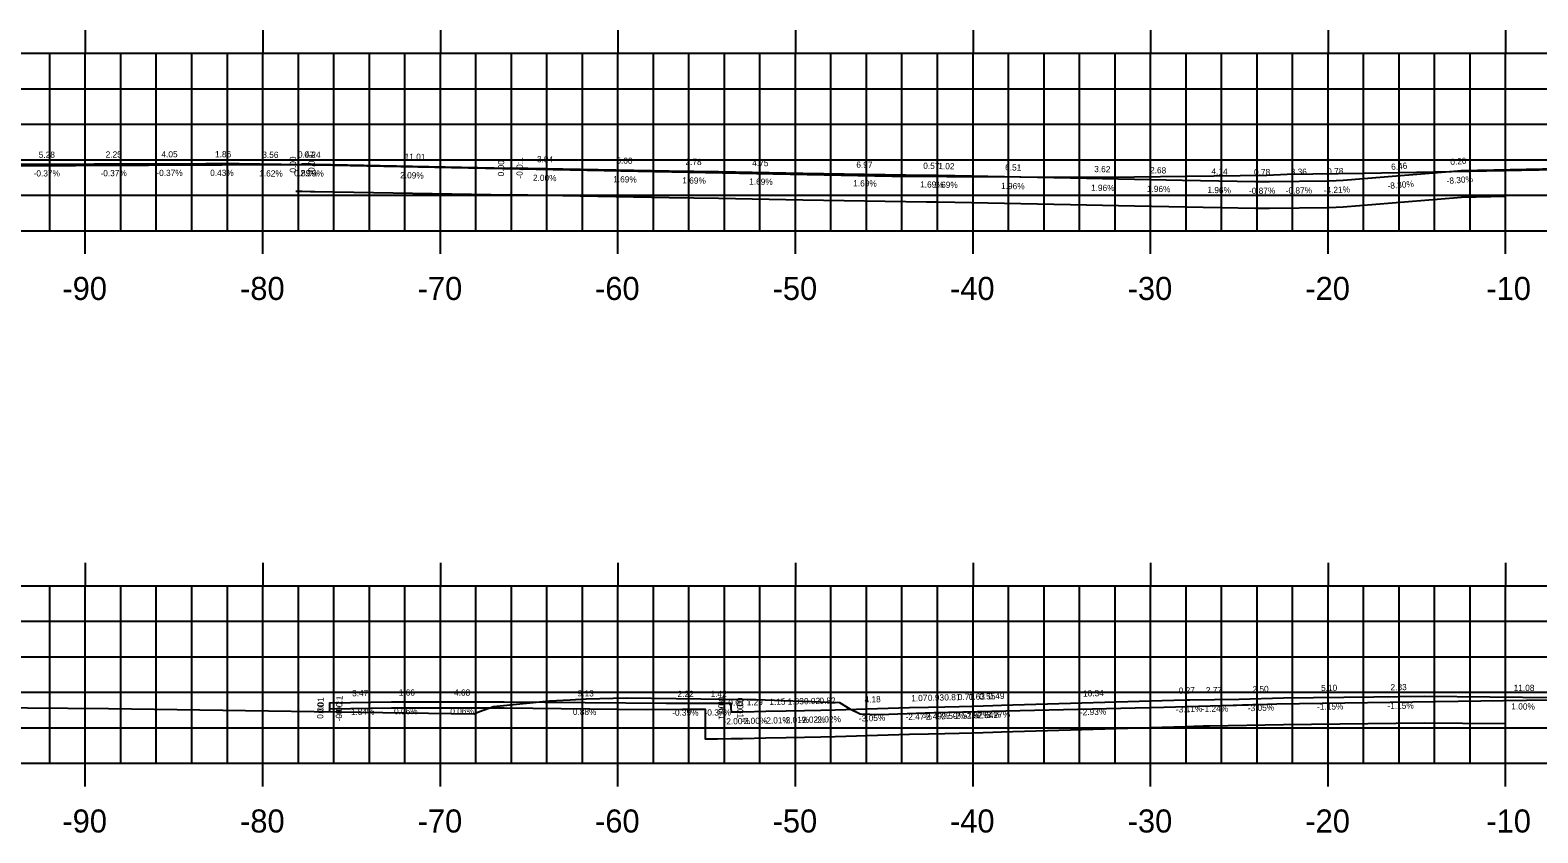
# Model space of a CAD drawing. Extents: x 40011 to 50684, y 49949 to 72236.
# Drawn here: x 41698.9 to 41783.8, y 69085.7 to 69130.9 of the extents above; entities that cross this region are included whole.
import ezdxf

# ---------------------------------------------------------------- set-up
doc = ezdxf.new("R2010")
doc.units = 0
for name, color, linetype in [('10', 7, 'Continuous'), ('51', 7, 'Continuous'), ('53', 7, 'Continuous'), ('55', 7, 'Continuous'), ('57', 7, 'Continuous'), ('58', 7, 'Continuous'), ('59', 7, 'Continuous'), ('60', 7, 'Continuous')]:
    doc.layers.add(name, color=color, linetype=linetype)

msp = doc.modelspace()

# ---------------------------------------------------------------- linework, layer by layer
at = {"layer": '51'}
for p, q in [((41699.977, 69119.597), (41699.977, 69129.597)), ((41703.977, 69119.597), (41703.977, 69129.597)), ((41705.977, 69119.597), (41705.977, 69129.597)), ((41707.977, 69119.597), (41707.977, 69129.597)), ((41709.977, 69119.597), (41709.977, 69129.597)), ((41713.977, 69119.597), (41713.977, 69129.597)), ((41715.977, 69119.597), (41715.977, 69129.597)), ((41717.977, 69119.597), (41717.977, 69129.597)), ((41719.977, 69119.597), (41719.977, 69129.597)), ((41723.977, 69119.597), (41723.977, 69129.597)), ((41725.977, 69119.597), (41725.977, 69129.597)), ((41727.977, 69119.597), (41727.977, 69129.597)), ((41729.977, 69119.597), (41729.977, 69129.597)), ((41733.977, 69119.597), (41733.977, 69129.597)), ((41735.977, 69119.597), (41735.977, 69129.597)), ((41737.977, 69119.597), (41737.977, 69129.597)), ((41739.977, 69119.597), (41739.977, 69129.597)), ((41743.977, 69119.597), (41743.977, 69129.597)), ((41745.977, 69119.597), (41745.977, 69129.597)), ((41747.977, 69119.597), (41747.977, 69129.597)), ((41749.977, 69119.597), (41749.977, 69129.597)), ((41753.977, 69119.597), (41753.977, 69129.597)), ((41755.977, 69119.597), (41755.977, 69129.597)), ((41757.977, 69119.597), (41757.977, 69129.597)), ((41759.977, 69119.597), (41759.977, 69129.597)), ((41763.977, 69119.597), (41763.977, 69129.597)), ((41765.977, 69119.597), (41765.977, 69129.597)), ((41767.977, 69119.597), (41767.977, 69129.597)), ((41769.977, 69119.597), (41769.977, 69129.597)), ((41773.977, 69119.597), (41773.977, 69129.597)), ((41775.977, 69119.597), (41775.977, 69129.597)), ((41777.977, 69119.597), (41777.977, 69129.597)), ((41779.977, 69119.597), (41779.977, 69129.597)), ((41651.977, 69119.597), (41931.977, 69119.597)), ((41701.977, 69118.297), (41701.977, 69119.597)), ((41711.977, 69118.297), (41711.977, 69119.597)), ((41721.977, 69118.297), (41721.977, 69119.597)), ((41731.977, 69118.297), (41731.977, 69119.597)), ((41741.977, 69118.297), (41741.977, 69119.597)), ((41751.977, 69118.297), (41751.977, 69119.597)), ((41761.977, 69118.297), (41761.977, 69119.597)), ((41771.977, 69118.297), (41771.977, 69119.597)), ((41781.977, 69118.297), (41781.977, 69119.597)), ((41699.977, 69089.597), (41699.977, 69099.597)), ((41703.977, 69089.597), (41703.977, 69099.597)), ((41705.977, 69089.597), (41705.977, 69099.597)), ((41707.977, 69089.597), (41707.977, 69099.597)), ((41709.977, 69089.597), (41709.977, 69099.597)), ((41713.977, 69089.597), (41713.977, 69099.597)), ((41715.977, 69089.597), (41715.977, 69099.597)), ((41717.977, 69089.597), (41717.977, 69099.597)), ((41719.977, 69089.597), (41719.977, 69099.597)), ((41723.977, 69089.597), (41723.977, 69099.597)), ((41725.977, 69089.597), (41725.977, 69099.597)), ((41727.977, 69089.597), (41727.977, 69099.597)), ((41729.977, 69089.597), (41729.977, 69099.597)), ((41733.977, 69089.597), (41733.977, 69099.597)), ((41735.977, 69089.597), (41735.977, 69099.597)), ((41737.977, 69089.597), (41737.977, 69099.597)), ((41739.977, 69089.597), (41739.977, 69099.597)), ((41743.977, 69089.597), (41743.977, 69099.597)), ((41745.977, 69089.597), (41745.977, 69099.597)), ((41747.977, 69089.597), (41747.977, 69099.597)), ((41749.977, 69089.597), (41749.977, 69099.597)), ((41753.977, 69089.597), (41753.977, 69099.597)), ((41755.977, 69089.597), (41755.977, 69099.597)), ((41757.977, 69089.597), (41757.977, 69099.597)), ((41759.977, 69089.597), (41759.977, 69099.597)), ((41763.977, 69089.597), (41763.977, 69099.597)), ((41765.977, 69089.597), (41765.977, 69099.597)), ((41767.977, 69089.597), (41767.977, 69099.597)), ((41769.977, 69089.597), (41769.977, 69099.597)), ((41773.977, 69089.597), (41773.977, 69099.597)), ((41775.977, 69089.597), (41775.977, 69099.597)), ((41777.977, 69089.597), (41777.977, 69099.597)), ((41779.977, 69089.597), (41779.977, 69099.597)), ((41651.977, 69089.597), (41931.977, 69089.597)), ((41701.977, 69088.297), (41701.977, 69089.597)), ((41711.977, 69088.297), (41711.977, 69089.597)), ((41721.977, 69088.297), (41721.977, 69089.597)), ((41731.977, 69088.297), (41731.977, 69089.597)), ((41741.977, 69088.297), (41741.977, 69089.597)), ((41751.977, 69088.297), (41751.977, 69089.597)), ((41761.977, 69088.297), (41761.977, 69089.597)), ((41771.977, 69088.297), (41771.977, 69089.597)), ((41781.977, 69088.297), (41781.977, 69089.597))]:
    msp.add_line(p, q, dxfattribs=at)
at = {"layer": '53'}
for p, q in [((41651.977, 69127.597), (41931.977, 69127.597)), ((41651.977, 69125.597), (41931.977, 69125.597)), ((41651.977, 69123.597), (41931.977, 69123.597)), ((41651.977, 69121.597), (41931.977, 69121.597)), ((41651.977, 69097.597), (41931.977, 69097.597)), ((41651.977, 69095.597), (41931.977, 69095.597)), ((41651.977, 69093.597), (41931.977, 69093.597)), ((41651.977, 69091.597), (41931.977, 69091.597))]:
    msp.add_line(p, q, dxfattribs=at)
at = {"layer": '55'}
for p, q in [((41651.977, 69129.597), (41931.977, 69129.597)), ((41701.977, 69119.597), (41701.977, 69129.597)), ((41711.977, 69119.597), (41711.977, 69129.597)), ((41721.977, 69119.597), (41721.977, 69129.597)), ((41731.977, 69119.597), (41731.977, 69129.597)), ((41741.977, 69119.597), (41741.977, 69129.597)), ((41751.977, 69119.597), (41751.977, 69129.597)), ((41761.977, 69119.597), (41761.977, 69129.597)), ((41771.977, 69119.597), (41771.977, 69129.597)), ((41781.977, 69119.597), (41781.977, 69129.597)), ((41651.977, 69119.597), (41931.977, 69119.597)), ((41651.977, 69099.597), (41931.977, 69099.597)), ((41701.977, 69089.597), (41701.977, 69099.597)), ((41711.977, 69089.597), (41711.977, 69099.597)), ((41721.977, 69089.597), (41721.977, 69099.597)), ((41731.977, 69089.597), (41731.977, 69099.597)), ((41741.977, 69089.597), (41741.977, 69099.597)), ((41751.977, 69089.597), (41751.977, 69099.597)), ((41761.977, 69089.597), (41761.977, 69099.597)), ((41771.977, 69089.597), (41771.977, 69099.597)), ((41781.977, 69089.597), (41781.977, 69099.597)), ((41651.977, 69089.597), (41931.977, 69089.597))]:
    msp.add_line(p, q, dxfattribs=at)
at = {"layer": '57'}
for points in [[(41697.294, 69123.263), (41713.798, 69123.331), (41714.122, 69123.332), (41714.313, 69123.328), (41714.451, 69123.326), (41714.601, 69123.322), (41714.666, 69123.321), (41714.751, 69123.319), (41714.882, 69123.317), (41714.984, 69123.315), (41747.396, 69122.672), (41749.41, 69122.663), (41750.509, 69122.658), (41752.836, 69122.646), (41754.624, 69122.632), (41756.899, 69122.624), (41758.486, 69122.622), (41759.551, 69122.623), (41768.536, 69122.729), (41769.676, 69122.782), (41773.986, 69122.844), (41790.784, 69123.162)], [(41682.714, 69092.853), (41703.291, 69092.676), (41723.886, 69092.381), (41724.177, 69092.506), (41724.971, 69092.802), (41728.118, 69093.122), (41729.28, 69093.178), (41730.181, 69093.236), (41732.482, 69093.294), (41739.435, 69093.2), (41739.7, 69093.196), (41739.766, 69093.2), (41742.34, 69093.101), (41744.457, 69093.024), (41745.032, 69092.666), (41745.614, 69092.381), (41746.707, 69092.35), (41748.269, 69092.394), (41749.785, 69092.453), (41762.732, 69092.753), (41766.634, 69092.873), (41766.828, 69092.878), (41767.148, 69092.886), (41767.282, 69092.888), (41767.496, 69092.894), (41767.748, 69092.905), (41767.832, 69092.91), (41768.042, 69092.914), (41769.087, 69092.947), (41781.853, 69093.126), (41792.221, 69093.276)]]:
    msp.add_lwpolyline(points, dxfattribs=at)
at = {"layer": '58'}
for points in [[(41713.829, 69121.826), (41713.867, 69121.826), (41714.04, 69121.824), (41714.179, 69121.822), (41714.196, 69121.822), (41714.663, 69121.814), (41714.907, 69121.81), (41725.917, 69121.625), (41725.917, 69121.638), (41729.859, 69121.559), (41734.859, 69121.474), (41737.638, 69121.427), (41742.393, 69121.347), (41749.359, 69121.229), (41749.927, 69121.219), (41750.948, 69121.202), (41757.46, 69121.075), (41761.08, 69121.004), (41765.919, 69120.909), (41767.896, 69120.87), (41768.677, 69120.877), (41772.035, 69120.906), (41772.82, 69120.939), (41779.276, 69121.476), (41779.477, 69121.492), (41779.491, 69121.492), (41781.978, 69121.542)], [(41715.756, 69092.665), (41719.228, 69092.729), (41720.888, 69092.728), (41725.564, 69092.725), (41733.605, 69092.631), (41735.617, 69092.637), (41736.883, 69092.641), (41736.891, 69091.778), (41736.897, 69090.972), (41737.24, 69090.975), (41737.58, 69090.979), (41738.347, 69090.988), (41739.016, 69091.001), (41740.308, 69091.027), (41741.459, 69091.05), (41742.485, 69091.071), (41743.402, 69091.089), (41744.221, 69091.106), (41748.398, 69091.233), (41749.464, 69091.259), (41750.392, 69091.282), (41751.202, 69091.302), (41751.914, 69091.321), (41752.541, 69091.336), (41753.095, 69091.351), (41753.581, 69091.366), (41763.923, 69091.669), (41764.189, 69091.677), (41764.419, 69091.684), (41764.619, 69091.691), (41764.794, 69091.696), (41764.948, 69091.701), (41765.084, 69091.705), (41765.205, 69091.709), (41765.313, 69091.712), (41769.463, 69091.788), (41777.394, 69091.879), (41779.546, 69091.857), (41781.933, 69091.833), (41781.977, 69091.833)]]:
    msp.add_lwpolyline(points, dxfattribs=at)
at = {"layer": '59'}
for points in [[(41697.191, 69123.345), (41702.475, 69123.365), (41704.725, 69123.373), (41708.772, 69123.388), (41710.635, 69123.38), (41714.196, 69123.323), (41714.196, 69123.365), (41714.663, 69123.361), (41714.906, 69123.356), (41725.917, 69123.126), (41725.917, 69123.139), (41729.86, 69123.06), (41734.859, 69122.976), (41737.638, 69122.929), (41742.393, 69122.848), (41749.359, 69122.731), (41749.926, 69122.721), (41750.947, 69122.704), (41757.46, 69122.576), (41761.08, 69122.505), (41763.756, 69122.453), (41767.896, 69122.371), (41768.677, 69122.378), (41772.035, 69122.408), (41772.819, 69122.441), (41779.281, 69122.977), (41779.477, 69122.993), (41790.477, 69123.213)], [(41715.74, 69092.495), (41715.745, 69092.636), (41715.756, 69092.995), (41719.228, 69093.059), (41720.888, 69093.058), (41725.563, 69093.055), (41734.697, 69092.975), (41736.915, 69092.984), (41738.333, 69092.989), (41738.341, 69092.729), (41738.347, 69092.489), (41739.017, 69092.502), (41740.309, 69092.528), (41741.459, 69092.551), (41742.485, 69092.572), (41743.402, 69092.59), (41744.221, 69092.607), (41748.398, 69092.734), (41749.464, 69092.761), (41750.391, 69092.784), (41751.202, 69092.804), (41751.913, 69092.822), (41752.541, 69092.838), (41753.095, 69092.852), (41753.581, 69092.868), (41763.923, 69093.171), (41764.188, 69093.179), (41766.96, 69093.213), (41769.463, 69093.289), (41774.561, 69093.348), (41777.394, 69093.38), (41788.477, 69093.269)]]:
    msp.add_lwpolyline(points, dxfattribs=at)
at = {"layer": '60'}
for p, q in [((41701.977, 69130.897), (41701.977, 69129.597)), ((41711.977, 69130.897), (41711.977, 69129.597)), ((41721.977, 69130.897), (41721.977, 69129.597)), ((41731.977, 69130.897), (41731.977, 69129.597)), ((41741.977, 69130.897), (41741.977, 69129.597)), ((41751.977, 69130.897), (41751.977, 69129.597)), ((41761.977, 69130.897), (41761.977, 69129.597)), ((41771.977, 69130.897), (41771.977, 69129.597)), ((41781.977, 69130.897), (41781.977, 69129.597)), ((41701.977, 69100.897), (41701.977, 69099.597)), ((41711.977, 69100.897), (41711.977, 69099.597)), ((41721.977, 69100.897), (41721.977, 69099.597)), ((41731.977, 69100.897), (41731.977, 69099.597)), ((41741.977, 69100.897), (41741.977, 69099.597)), ((41751.977, 69100.897), (41751.977, 69099.597)), ((41761.977, 69100.897), (41761.977, 69099.597)), ((41771.977, 69100.897), (41771.977, 69099.597)), ((41781.977, 69100.897), (41781.977, 69099.597))]:
    msp.add_line(p, q, dxfattribs=at)

# ---------------------------------------------------------------- texts
at = {"layer": '10'}
for s, rotation, p in [('5.28', 0.21204, (41699.355, 69123.703)), ('2.25', 0.21204, (41703.123, 69123.717)), ('4.05', 0.21204, (41706.266, 69123.729)), ('1.86', 359.75548, (41709.282, 69123.736)), ('3.56', 359.07277, (41711.943, 69123.709)), ('0.00', 89.4803, (41713.842, 69122.869)), ('0.47', 359.48778, (41713.954, 69123.717)), ('0.24', 358.80512, (41714.315, 69123.718)), ('-0.0:1', 89.4803, (41714.891, 69122.749)), ('11.01', 358.80512, (41719.962, 69123.601)), ('3.94', 358.85582, (41727.415, 69123.459)), ('-0.37%', 0.21204, (41699.065, 69122.652)), ('-0.37%', 0.21204, (41702.832, 69122.666)), ('-0.37%', 0.21204, (41705.98, 69122.678)), ('0.43%', 359.75548, (41709.01, 69122.687)), ('1.62%', 359.07277, (41711.771, 69122.662)), ('0.89%', 359.48778, (41713.735, 69122.669)), ('2.09%', 358.80512, (41714.082, 69122.673)), ('2.09%', 358.80512, (41719.709, 69122.556)), ('0.00', 89.29638, (41725.561, 69122.659)), ('-0.0:1', 89.29638, (41726.61, 69122.535)), ('5.00', 359.03149, (41731.887, 69123.376)), ('2.78', 359.03149, (41735.779, 69123.31)), ('4.75', 359.03149, (41739.542, 69123.247)), ('6.97', 359.03149, (41745.403, 69123.147)), ('0.57', 359.03149, (41749.172, 69123.084)), ('1.02', 359.03149, (41750.023, 69123.069)), ('6.51', 358.87667, (41753.784, 69122.998)), ('3.62', 358.87667, (41758.8, 69122.9)), ('2.68', 358.87667, (41761.947, 69122.838)), ('4.14', 358.87667, (41765.406, 69122.77)), ('0.78', 0.50084, (41767.807, 69122.721)), ('3.36', 0.50084, (41769.874, 69122.739)), ('0.78', 2.41136, (41771.936, 69122.754)), ('6.46', 4.74373, (41775.541, 69123.018)), ('0.20', 4.74394, (41778.875, 69123.294)), ('2.00%', 358.85582, (41727.188, 69122.413)), ('1.69%', 359.03149, (41731.711, 69122.329)), ('1.69%', 359.03149, (41735.601, 69122.263)), ('1.69%', 359.03149, (41739.367, 69122.199)), ('1.69%', 359.03149, (41745.228, 69122.1)), ('1.69%', 359.03149, (41748.995, 69122.037)), ('1.69%', 359.03149, (41749.789, 69122.023)), ('1.96%', 358.87667, (41753.554, 69121.952)), ('1.96%', 358.87667, (41758.62, 69121.853)), ('1.96%', 358.87667, (41761.768, 69121.791)), ('1.96%', 358.87667, (41765.176, 69121.725)), ('-0.87%', 0.50084, (41769.592, 69121.686)), ('-4.21%', 2.41136, (41771.739, 69121.694)), ('-8.30%', 4.74373, (41775.339, 69121.947)), ('-8.30%', 4.74394, (41778.668, 69122.224)), ('-0.87%', 0.50084, (41767.523, 69121.668)), ('5.10', 0.6579, (41771.584, 69093.664)), ('2.83', 0.6579, (41775.497, 69093.709)), ('11.08', 359.42484, (41782.429, 69093.68)), ('0.01', 88.21171, (41715.387, 69092.402)), ('-0.0:1', 88.21171, (41716.432, 69092.205)), ('3.47', 1.054, (41717.006, 69093.368)), ('1.66', 359.96429, (41719.633, 69093.409)), ('4.68', 359.96429, (41722.744, 69093.407)), ('9.13', 359.49803, (41729.708, 69093.369)), ('2.22', 0.22295, (41735.333, 69093.327)), ('1.42', 0.21313, (41737.2, 69093.335)), ('0.0:1', 271.64386, (41737.623, 69093.344)), ('0.67', 1.14584, (41738.198, 69092.836)), ('0.01', 271.64386, (41738.675, 69093.294)), ('1.29', 1.14819, (41739.234, 69092.857)), ('1.15', 1.1507, (41740.508, 69092.882)), ('1.03', 1.1534, (41741.542, 69092.903)), ('0.92', 1.15628, (41742.461, 69092.922)), ('0.82', 1.15938, (41743.331, 69092.939)), ('4.18', 1.74432, (41745.873, 69093.008)), ('1.07', 1.41764, (41748.501, 69093.087)), ('0.93', 1.42404, (41749.44, 69093.11)), ('0.81', 1.43091, (41750.364, 69093.133)), ('0.71', 1.4383, (41751.125, 69093.152)), ('0.63', 1.44624, (41751.739, 69093.168)), ('0.55', 1.45477, (41752.331, 69093.182)), ('0.49', 1.8717, (41752.846, 69093.194)), ('10.34', 1.67787, (41758.177, 69093.352)), ('0.27', 1.78398, (41763.57, 69093.51)), ('2.77', 0.70834, (41765.096, 69093.54)), ('2.50', 1.74471, (41767.724, 69093.587)), ('0.00', 88.21171, (41715.378, 69092.099)), ('-0.0:1', 88.21171, (41716.424, 69091.955)), ('-1.84%', 1.054, (41716.785, 69092.314)), ('0.06%', 359.96429, (41719.368, 69092.359)), ('0.06%', 359.96429, (41722.536, 69092.357)), ('0.88%', 359.49803, (41729.437, 69092.321)), ('-0.39%', 0.22295, (41735.035, 69092.276)), ('-0.37%', 0.21313, (41736.856, 69092.283)), ('0.0:1', 271.64389, (41737.63, 69093.094)), ('0.01', 271.64389, (41738.682, 69093.044)), ('-3.05%', 1.74432, (41745.559, 69091.947)), ('-2.47%', 1.41764, (41748.177, 69092.029)), ('-2.49%', 1.42404, (41749.171, 69092.053)), ('-2.50%', 1.43091, (41750.044, 69092.075)), ('-2.51%', 1.4383, (41750.859, 69092.095)), ('-2.52%', 1.44624, (41751.476, 69092.111)), ('-2.54%', 1.45477, (41752.062, 69092.125)), ('-3.27%', 1.8717, (41752.592, 69092.135)), ('-2.93%', 1.67787, (41758.001, 69092.297)), ('-3.11%', 1.78398, (41763.414, 69092.454)), ('-1.24%', 0.70834, (41764.864, 69092.487)), ('-3.05%', 1.74471, (41767.461, 69092.528)), ('-1.15%', 0.6579, (41771.357, 69092.611)), ('-1.15%', 0.6579, (41775.322, 69092.657)), ('1.00%', 359.42484, (41782.295, 69092.631)), ('-2.00%', 1.14584, (41737.926, 69091.78)), ('-2.00%', 1.14819, (41738.907, 69091.8)), ('-2.01%', 1.1507, (41740.182, 69091.826)), ('-2.01%', 1.1534, (41741.271, 69091.847)), ('-2.02%', 1.15628, (41742.189, 69091.866)), ('-2.02%', 1.15938, (41743.057, 69091.883))]:
    msp.add_text(s, height=0.35, rotation=rotation, dxfattribs=at).set_placement(p)
at = {"layer": '51'}
for s, p in [('-90', (41700.686, 69115.697)), ('-80', (41710.693, 69115.697)), ('-70', (41720.695, 69115.697)), ('-60', (41730.686, 69115.697)), ('-50', (41740.689, 69115.697)), ('-40', (41750.68, 69115.697)), ('-30', (41760.688, 69115.697)), ('-20', (41770.695, 69115.697)), ('-10', (41780.892, 69115.697)), ('-90', (41700.686, 69085.697)), ('-80', (41710.693, 69085.697)), ('-70', (41720.695, 69085.697)), ('-60', (41730.686, 69085.697)), ('-50', (41740.689, 69085.697)), ('-40', (41750.68, 69085.697)), ('-30', (41760.688, 69085.697)), ('-20', (41770.695, 69085.697)), ('-10', (41780.892, 69085.697))]:
    msp.add_text(s, height=1.3, dxfattribs=at).set_placement(p)

doc.saveas('drawing.dxf')
